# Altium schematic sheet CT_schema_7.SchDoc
size 287 x 160 mm
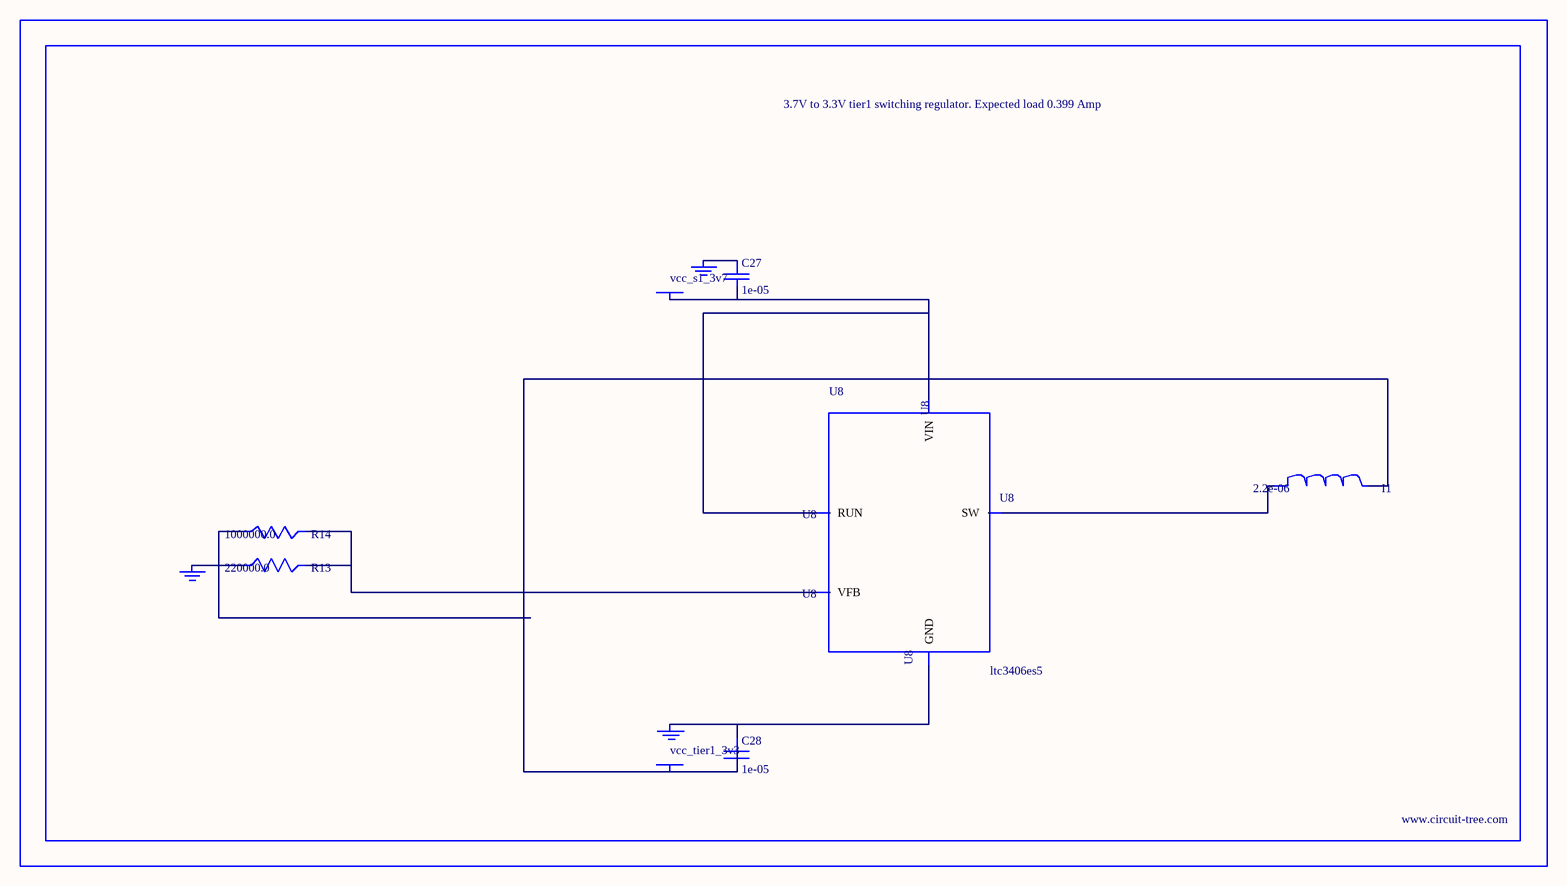
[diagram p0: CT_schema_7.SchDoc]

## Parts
BORDER6  (no value)
C27  1e-05  [C0805]
C28  1e-05  [C0805]
GND_INSTANCE_6_0  (no value)
GND_INSTANCE_6_1  (no value)
GND_INSTANCE_6_2  (no value)
I1  2.2e-06  [L0805]
POWER_INSTANCE_6_0  vcc_tier1_3v3
POWER_INSTANCE_6_1  vcc_s1_3v7
R13  220000.0  [R0603]
R14  1000000.0  [R0603]
U8  ltc3406es5  [TSOT-23-5]

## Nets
NetC27_1: C27.1 GND_INSTANCE_6_1.0(GND)
NetC27_2: C27.2 POWER_INSTANCE_6_1.0(PWR) U8.1(RUN) U8.4(VIN)
NetC28_1: C28.1 GND_INSTANCE_6_0.0(GND) U8.2(GND)
NetC28_2: C28.2 I1.2 POWER_INSTANCE_6_0.0(PWR) R14.1
NetGND_INSTANCE_6_2_0: GND_INSTANCE_6_2.0(GND) R13.1
NetI1_1: I1.1 U8.3(SW)
NetR13_2: R13.2 R14.2 U8.5(VFB)

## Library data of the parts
BORDER6 = BORDER_PAGE6
C27 C28 = C0805C106K8RACTU
GND_INSTANCE_6_0-GND_INSTANCE_6_2 = GND
I1 = L0805C2R2MDWIT
POWER_INSTANCE_6_0 POWER_INSTANCE_6_1 = PWR
R13 = RC0603JR-07220KL
R14 = RC0603JR-071ML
